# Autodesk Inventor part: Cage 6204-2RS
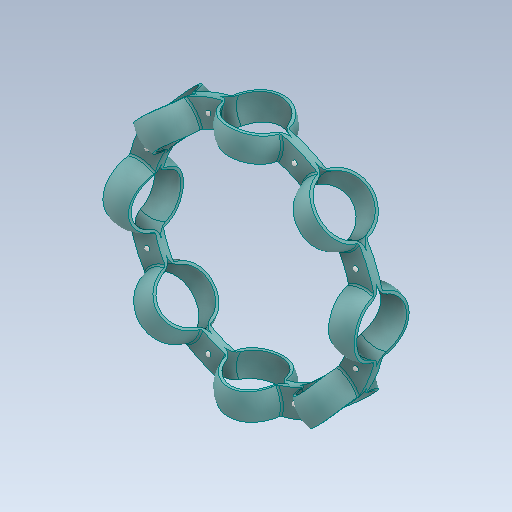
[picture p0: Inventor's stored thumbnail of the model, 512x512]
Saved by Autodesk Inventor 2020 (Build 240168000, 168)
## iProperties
Created: 2001-06
Part Number: Cage 6204-2RS
Material: Générique
Document SubType Name: Modeling
Designer: Bruno
Density: 1 g/cm^3
Appearance: Par défaut
Author: Bruno
Sending System: SolidWorks 2011
Last Author: frederic
Last Saved: 2012-02-20
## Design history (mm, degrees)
feature "Bossage-Symétrie1"
node "Solide1"
